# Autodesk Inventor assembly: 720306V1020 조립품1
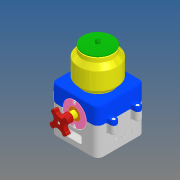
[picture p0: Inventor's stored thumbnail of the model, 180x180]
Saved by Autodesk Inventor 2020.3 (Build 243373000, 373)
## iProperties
Created: 2022-03
Part Number: 720306V1020 조립품1
Document SubType Name: Assembly
Designer: EZDESIGN
Author: EZDESIGN
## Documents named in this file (11)
- C:\Users\EZDESIGN\Desktop\720306V1020\720306V1020\720306V1020 조립품1.iam
- C:\Users\EZDESIGN\Desktop\720306V1020\720306V1020\720306V1020 본체.ipt
- C:\Users\EZDESIGN\Desktop\720306V1020\720306V1020\베어링 부시.ipt
- C:\Users\EZDESIGN\Desktop\720306V1020\720306V1020\본체커버.ipt
- C:\Users\EZDESIGN\Desktop\720306V1020\720306V1020\볼트 M3x12.ipt
- C:\Users\EZDESIGN\Desktop\720306V1020\720306V1020\볼트 M4x12.ipt
- C:\Users\EZDESIGN\Desktop\720306V1020\720306V1020\앞커버.ipt
- C:\Users\EZDESIGN\Desktop\720306V1020\720306V1020\용기.ipt
- C:\Users\EZDESIGN\Desktop\720306V1020\720306V1020\용기캡.ipt
- C:\Users\EZDESIGN\Desktop\720306V1020\720306V1020\핸들.ipt
- C:\Users\EZDESIGN\Desktop\720306V1020\720306V1020\핸들축.ipt
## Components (3 placed, 3 different names)
1. 720306V1020 본체:1
2. 핸들축:1
3. 핸들:1
